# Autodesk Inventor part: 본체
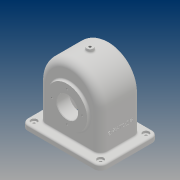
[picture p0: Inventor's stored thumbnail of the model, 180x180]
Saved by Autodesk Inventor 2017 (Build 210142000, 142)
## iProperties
Part Number: 본체
Material: 일반
Document SubType Name: Modeling
Designer: 20
Density: 1 g/cm^3
Appearance: 기본값
Mass: 404.475 g
Surface Area: 1182.21 cm^2
Volume: 404.475 cm^3
Author: 20
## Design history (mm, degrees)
sketch "스케치1"
  geometry: L1 (58, 0)-(58, -78); L2 (58, -78)-(-58, -78); L3 (-58, -78)-(-58, 0); A1 r 58 centre (0, 0) between (58, 0) and (-58, 0); 1 further point
  constraints: 6 end point, 2 point on circle, 2 tangent, 2 vertical, 1 centre point, 1 coincident, 1 horizontal
  dimensions: "d0" = 116 diameter of A1; "d1" = 78 distance from line of L2 point (0, 0)
extrude "돌출1" new body sketch "스케치1" stored distance "d2" = 77; taper "d3" = 0 deg
sketch "스케치3"
  geometry: L1 (52, 3.665)-(52, -78); L2 (52, -78)-(-52, -78); L3 (-52, -78)-(-52, 0); A1 r 52 centre (0, 0) between (52, 0) and (-52, 0); A2 r 58 centre (0, 0) between (58, 0) and (-58, 0) reference; 1 further point
  constraints: 6 end point, 2 point on circle, 2 tangent, 2 vertical, 1 centre point, 1 concentric, 1 horizontal, 1 point on line
  dimensions: "d8" = 104 diameter of A1; "d9" = 78 distance from line of L2 point (0, 0)
extrude "돌출3" cut sketch "스케치3" stored distance "d10" = 67; taper "d11" = 0 deg
sketch "스케치4"
  geometry: L1 (-58, -78)-(58, -78) reference; C1 r 38 at (0, -13); 1 further point
  constraints: 1 centre point, 1 vertical alignment
  dimensions: "d12" = 76 diameter of C1; "d13" = 65 distance from line of L1 C1.centre
extrude "돌출4" join sketch "스케치4" distance "d14" = 5; taper "d15" = 0 deg
sketch "스케치5"
  geometry: L1 (-58, 78)-(58, 78) reference; C1 r 28 at (0, 13); 1 further point
  constraints: 1 centre point, 1 vertical alignment
  dimensions: "d16" = 56 diameter of C1; "d17" = 65 distance from line of L1 C1.centre
extrude "돌출5" join sketch "스케치5" distance "d18" = 14; taper "d19" = 0 deg
feature "면 기울기1" dims angle "d20" = 40 deg
sketch "스케치6"
  geometry: L1 (58, 78)-(-58, 78) reference; C1 r 38 at (0, 13); 1 further point
  constraints: 1 centre point, 1 vertical alignment
  dimensions: "d21" = 76 diameter of C1; "d22" = 65 distance from line of L1 C1.centre
extrude "돌출6" join sketch "스케치6" distance "d23" = 10; taper "d24" = 0 deg
sketch "스케치7"
  geometry: C1 r 20 at (0, 0); C2 r 38 at (0, 0) reference; 1 further point
  constraints: 1 centre point, 1 concentric
  dimensions: "d25" = 40 diameter of C1
extrude "돌출7" cut sketch "스케치7" stored distance "d26" = 10; taper "d27" = 0 deg
sketch "스케치8"
  geometry: L1 (-17, -93.5)-(133, -93.5); L2 (133, -93.5)-(133, 16.5); L3 (133, 16.5)-(-17, 16.5); L4 (-17, 16.5)-(-17, -93.5); L5 (-17, -93.5)-(133, 16.5); L6 (133, -93.5)-(-17, 16.5); L7 (0, 0)-(116, 0) reference; L8 (0, 0)-(0, -77) reference; L9 (116, -77)-(0, -77) reference; L10 (116, 0)-(116, -77) reference; 1 further point
  constraints: 12 end point, 2 midpoint, 2 parallel, 1 horizontal, 1 perpendicular
  dimensions: "d28" = 150 distance of L2.end L3.end; "d29" = 110 distance of L3.end L1.start
extrude "돌출8" join sketch "스케치8" distance "d30" = 10; taper "d31" = 0 deg
node "작업 평면1"
sketch "스케치9"
  geometry: C1 r 6 at (75, 55); 1 further point
  constraints: 1 centre point, 1 coincident
  dimensions: "d33" = 12 diameter of C1
extrude "돌출9" join sketch "스케치9" distance "d34" = 10; taper "d35" = 5 deg
fillet "모깎기1" dims "d36" = 12
hole "구멍1" diameter "d39" = 5; stored, may be unused: countersink angle "d43" = 90 deg, drill point angle "d45" = 118 deg; dims "d37" = 10, "d38" = 10, "d40" = 6.35, "d41" = 12, "d42" = 4, "d44" = 9.525
hole "구멍2" diameter "d48" = 5; stored, may be unused: countersink angle "d52" = 90 deg, drill point angle "d54" = 118 deg; dims "d46" = 10, "d47" = 10, "d49" = 6.35, "d50" = 12, "d51" = 4, "d53" = 9.525
hole "구멍3" diameter "d57" = 5; stored, may be unused: countersink angle "d61" = 90 deg, drill point angle "d63" = 118 deg; dims "d55" = 10, "d56" = 10, "d58" = 6.35, "d59" = 12, "d60" = 4, "d62" = 9.525
hole "구멍4" diameter "d66" = 5; stored, may be unused: countersink angle "d70" = 90 deg, drill point angle "d72" = 118 deg; dims "d64" = 10, "d65" = 10, "d67" = 6.35, "d68" = 12, "d69" = 4, "d71" = 9.525
sketch "스케치10" dims "d73" = 58
  geometry: C1 r 38 at (0, 0) reference; 3 further points
  constraints: 2 vertical alignment, 3 other
hole "구멍5" sketch "스케치10" at (0, 29) diameter "d74" = 3.242; stored, may be unused: countersink angle "d78" = 90 deg, drill point angle "d80" = 118 deg; dims "d75" = 8, "d76" = 12, "d77" = 4, "d79" = 10
sketch "스케치11" dims "d84" = 58
  geometry: C1 r 38 at (0, 0) reference; 3 further points
  constraints: 2 vertical alignment, 3 other
hole "구멍6" sketch "스케치11" at (0, -29) diameter "d85" = 3.242; stored, may be unused: countersink angle "d89" = 90 deg, drill point angle "d91" = 118 deg; dims "d86" = 8, "d87" = 12, "d88" = 4, "d90" = 10
fillet "모깎기2" dims "d95" = 13
fillet "모깎기3" dims "d96" = 8
fillet "모깎기4" dims "d97" = 3
fillet "모깎기5" dims "d98" = 3
fillet "모깎기6" dims "d99" = 3
fillet "모깎기7" dims "d100" = 3
chamfer "모따기1" distance "d101" = 1; stored, may be unused: second distance "d102" = 2, angle "d103" = 45 deg
hole "구멍7" diameter "d106" = 4.459; stored, may be unused: countersink angle "d110" = 90 deg, drill point angle "d112" = 118 deg; dims "d104" = 10, "d105" = 10, "d107" = 30, "d108" = 12, "d109" = 4, "d111" = 12.8
sketch "스케치12"
  geometry: L1 (0, -13)-(65, -13) reference; L2 (78, 68.5)-(78, -17.5) reference; 2 further points
  constraints: 1 other
  dimensions: "d113" = 38.5 distance from line of point (38, 25.5) L1; "d114" = 40 distance from line of L2 point (38, 25.5)
feature "엠보싱1" sketch "스케치12" dims "d115" = 0.5, "d116" = 0
fillet "모깎기8" dims "d117" = 3
node "솔리드1"
pattern_circular "원형 패턴1" dims angle "d82" = 360 deg
pattern_circular "원형 패턴2" dims angle "d93" = 360 deg
other parameters: "d32" = -142
